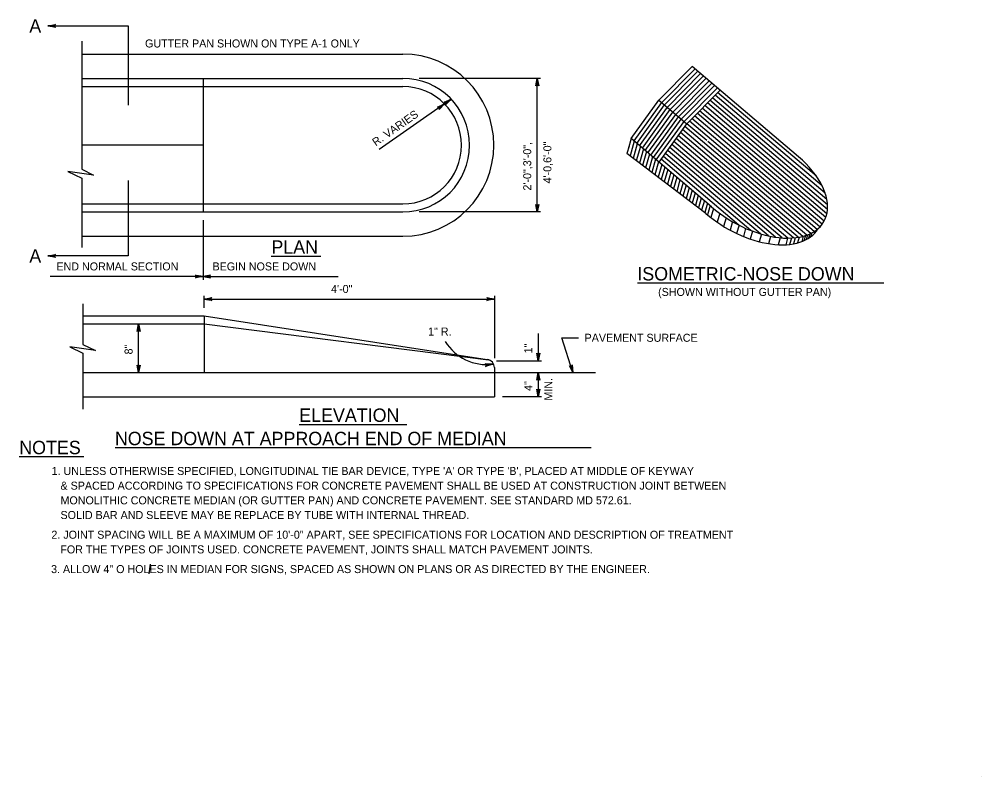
# Model space of a CAD drawing. Extents: x -49.1 to -41.9, y 44.5 to 54.6.
# Drawn here: x -49.07 to -41.86, y 44.46 to 50.14 of the extents above; entities that cross this region are included whole.
import ezdxf

# ---------------------------------------------------------------- set-up
doc = ezdxf.new("R2010")
doc.units = 0
for name, color, linetype in [('DETL-DIMS', 7, 'Continuous'), ('DETL-LINE', 7, 'Continuous'), ('DETL-NOTE', 7, 'Continuous'), ('DETL-PATT', 7, 'Continuous'), ('DETL-TITL', 7, 'Continuous'), ('TTLB-TEXT', 7, 'Continuous')]:
    doc.layers.add(name, color=color, linetype=linetype)

msp = doc.modelspace()

# ---------------------------------------------------------------- linework, layer by layer
at = {"layer": 'DETL-DIMS'}
for p, q in [((-48.8553, 50.0858), (-48.2538, 50.0858)), ((-48.2539, 50.0858), (-48.2539, 49.4918)), ((-45.1641, 49.6931), (-46.0747, 49.6931)), ((-45.1883, 48.6931), (-45.1883, 49.6931)), ((-45.8839, 49.5024), (-46.3726, 49.1601)), ((-45.8328, 49.5381), (-45.8838, 49.5024)), ((-48.2539, 48.9286), (-48.2539, 48.3637)), ((-45.1641, 48.6931), (-46.0747, 48.6931)), ((-47.6925, 48.6325), (-47.6925, 48.1858)), ((-48.2539, 48.3637), (-48.8553, 48.3637)), ((-47.6925, 48.2101), (-48.8389, 48.2101)), ((-47.6925, 48.2101), (-46.6795, 48.2101)), ((-47.6848, 47.9757), (-47.6848, 48.0656)), ((-47.6848, 48.0413), (-45.5099, 48.0413)), ((-45.5099, 48.0656), (-45.5099, 47.5984)), ((-48.1756, 47.4909), (-48.1756, 47.8545)), ((-45.1812, 47.7826), (-45.1812, 47.5795)), ((-44.9211, 47.491), (-45.0044, 47.7513)), ((-45.0044, 47.7513), (-44.8795, 47.7513)), ((-45.495, 47.5795), (-45.157, 47.5795)), ((-45.1812, 47.4909), (-45.1812, 47.3091)), ((-45.157, 47.3091), (-45.4493, 47.3091))]:
    msp.add_line(p, q, dxfattribs=at)
for points in [[(-48.8553, 50.0858), (-48.7988, 50.0964), (-48.8031, 50.0934), (-48.8054, 50.0896), (-48.806, 50.0858), (-48.8054, 50.0821), (-48.8031, 50.0783), (-48.7988, 50.0752), (-48.8553, 50.0858), (-48.8031, 50.0783), (-48.8054, 50.0821), (-48.8553, 50.0858), (-48.806, 50.0858), (-48.8054, 50.0896), (-48.8553, 50.0858), (-48.8031, 50.0934)], [(-45.1883, 49.6931), (-45.1777, 49.6366), (-45.1807, 49.6409), (-45.1845, 49.6432), (-45.1883, 49.6438), (-45.1921, 49.6432), (-45.1959, 49.6409), (-45.1989, 49.6366), (-45.1883, 49.6931), (-45.1959, 49.6409), (-45.1921, 49.6432), (-45.1883, 49.6931), (-45.1883, 49.6438), (-45.1845, 49.6432), (-45.1883, 49.6931), (-45.1807, 49.6409)], [(-45.1883, 49.6931), (-45.1777, 49.6366), (-45.1807, 49.6409), (-45.1845, 49.6432), (-45.1883, 49.6438), (-45.1921, 49.6432), (-45.1959, 49.6409), (-45.1989, 49.6366), (-45.1883, 49.6931), (-45.1959, 49.6409), (-45.1921, 49.6432), (-45.1883, 49.6931), (-45.1883, 49.6438), (-45.1845, 49.6432), (-45.1883, 49.6931), (-45.1807, 49.6409)], [(-45.8839, 49.5024), (-45.9241, 49.4613), (-45.9222, 49.4662), (-45.9226, 49.4706), (-45.9242, 49.4741), (-45.9269, 49.4769), (-45.9309, 49.4787), (-45.9362, 49.4786), (-45.8839, 49.5024), (-45.9309, 49.4787), (-45.9269, 49.4769), (-45.8839, 49.5024), (-45.9242, 49.4741), (-45.9226, 49.4706), (-45.8839, 49.5024), (-45.9222, 49.4662)], [(-45.8328, 49.5381), (-45.873, 49.497), (-45.8712, 49.502), (-45.8715, 49.5064), (-45.8732, 49.5099), (-45.8759, 49.5126), (-45.8799, 49.5144), (-45.8852, 49.5144), (-45.8328, 49.5381), (-45.8799, 49.5144), (-45.8759, 49.5126), (-45.8328, 49.5381), (-45.8732, 49.5099), (-45.8715, 49.5064), (-45.8328, 49.5381), (-45.8712, 49.502)], [(-45.1883, 48.6931), (-45.1989, 48.7496), (-45.1959, 48.7452), (-45.1921, 48.743), (-45.1883, 48.7423), (-45.1845, 48.743), (-45.1807, 48.7452), (-45.1777, 48.7496), (-45.1883, 48.6931), (-45.1807, 48.7452), (-45.1845, 48.743), (-45.1883, 48.6931), (-45.1883, 48.7423), (-45.1921, 48.743), (-45.1883, 48.6931), (-45.1959, 48.7452)], [(-48.8553, 48.3637), (-48.7988, 48.3743), (-48.8031, 48.3712), (-48.8054, 48.3675), (-48.806, 48.3637), (-48.8054, 48.3599), (-48.8031, 48.3561), (-48.7988, 48.3531), (-48.8553, 48.3637), (-48.8031, 48.3561), (-48.8054, 48.3599), (-48.8553, 48.3637), (-48.806, 48.3637), (-48.8054, 48.3675), (-48.8553, 48.3637), (-48.8031, 48.3712)], [(-47.6925, 48.2101), (-47.7489, 48.1995), (-47.7446, 48.2025), (-47.7423, 48.2063), (-47.7417, 48.2101), (-47.7423, 48.2139), (-47.7446, 48.2176), (-47.7489, 48.2207), (-47.6925, 48.2101), (-47.7446, 48.2176), (-47.7423, 48.2139), (-47.6925, 48.2101), (-47.7417, 48.2101), (-47.7423, 48.2063), (-47.6925, 48.2101), (-47.7446, 48.2025)], [(-47.6925, 48.2101), (-47.636, 48.1995), (-47.6403, 48.2025), (-47.6426, 48.2063), (-47.6432, 48.2101), (-47.6426, 48.2139), (-47.6403, 48.2176), (-47.636, 48.2207), (-47.6925, 48.2101), (-47.6403, 48.2176), (-47.6426, 48.2139), (-47.6925, 48.2101), (-47.6432, 48.2101), (-47.6426, 48.2063), (-47.6925, 48.2101), (-47.6403, 48.2025)], [(-47.6848, 48.0413), (-47.6283, 48.0519), (-47.6326, 48.0489), (-47.6349, 48.0451), (-47.6355, 48.0413), (-47.6349, 48.0375), (-47.6326, 48.0337), (-47.6283, 48.0307), (-47.6848, 48.0413), (-47.6326, 48.0337), (-47.6349, 48.0375), (-47.6848, 48.0413), (-47.6355, 48.0413), (-47.6349, 48.0451), (-47.6848, 48.0413), (-47.6326, 48.0489)], [(-47.6848, 48.0413), (-47.6283, 48.0519), (-47.6326, 48.0489), (-47.6349, 48.0451), (-47.6355, 48.0413), (-47.6349, 48.0375), (-47.6326, 48.0337), (-47.6283, 48.0307), (-47.6848, 48.0413), (-47.6326, 48.0337), (-47.6349, 48.0375), (-47.6848, 48.0413), (-47.6355, 48.0413), (-47.6349, 48.0451), (-47.6848, 48.0413), (-47.6326, 48.0489)], [(-45.5099, 48.0413), (-45.5664, 48.0307), (-45.562, 48.0337), (-45.5598, 48.0375), (-45.5591, 48.0413), (-45.5598, 48.0451), (-45.562, 48.0489), (-45.5664, 48.0519), (-45.5099, 48.0413), (-45.562, 48.0489), (-45.5598, 48.0451), (-45.5099, 48.0413), (-45.5591, 48.0413), (-45.5598, 48.0375), (-45.5099, 48.0413), (-45.562, 48.0337)], [(-48.1756, 47.8545), (-48.165, 47.798), (-48.168, 47.8024), (-48.1718, 47.8046), (-48.1756, 47.8053), (-48.1794, 47.8046), (-48.1831, 47.8024), (-48.1861, 47.798), (-48.1756, 47.8545), (-48.1831, 47.8024), (-48.1794, 47.8046), (-48.1756, 47.8545), (-48.1756, 47.8053), (-48.1718, 47.8046), (-48.1756, 47.8545), (-48.168, 47.8024)], [(-48.1756, 47.8545), (-48.165, 47.798), (-48.168, 47.8024), (-48.1718, 47.8046), (-48.1756, 47.8053), (-48.1794, 47.8046), (-48.1831, 47.8024), (-48.1861, 47.798), (-48.1756, 47.8545), (-48.1831, 47.8024), (-48.1794, 47.8046), (-48.1756, 47.8545), (-48.1756, 47.8053), (-48.1718, 47.8046), (-48.1756, 47.8545), (-48.168, 47.8024)], [(-45.1812, 47.5795), (-45.1918, 47.636), (-45.1888, 47.6317), (-45.185, 47.6294), (-45.1812, 47.6288), (-45.1774, 47.6294), (-45.1737, 47.6317), (-45.1706, 47.636), (-45.1812, 47.5795), (-45.1737, 47.6317), (-45.1774, 47.6294), (-45.1812, 47.5795), (-45.1812, 47.6288), (-45.185, 47.6294), (-45.1812, 47.5795), (-45.1888, 47.6317)], [(-45.1812, 47.5795), (-45.1918, 47.636), (-45.1888, 47.6317), (-45.185, 47.6294), (-45.1812, 47.6288), (-45.1774, 47.6294), (-45.1737, 47.6317), (-45.1706, 47.636), (-45.1812, 47.5795), (-45.1737, 47.6317), (-45.1774, 47.6294), (-45.1812, 47.5795), (-45.1812, 47.6288), (-45.185, 47.6294), (-45.1812, 47.5795), (-45.1888, 47.6317)], [(-48.1756, 47.4909), (-48.1861, 47.5474), (-48.1831, 47.543), (-48.1794, 47.5408), (-48.1756, 47.5401), (-48.1718, 47.5408), (-48.168, 47.543), (-48.165, 47.5474), (-48.1756, 47.4909), (-48.168, 47.543), (-48.1718, 47.5408), (-48.1756, 47.4909), (-48.1756, 47.5401), (-48.1794, 47.5408), (-48.1756, 47.4909), (-48.1831, 47.543)], [(-45.522, 47.5535), (-45.5766, 47.5356), (-45.5727, 47.5392), (-45.571, 47.5433), (-45.5708, 47.5471), (-45.572, 47.5508), (-45.5747, 47.5542), (-45.5794, 47.5566), (-45.522, 47.5535), (-45.5747, 47.5542), (-45.572, 47.5508), (-45.522, 47.5535), (-45.5708, 47.5471), (-45.571, 47.5433), (-45.522, 47.5535), (-45.5727, 47.5392)], [(-44.9211, 47.491), (-44.9484, 47.5416), (-44.9442, 47.5384), (-44.9399, 47.5374), (-44.9361, 47.5379), (-44.9327, 47.5397), (-44.9298, 47.543), (-44.9282, 47.5481), (-44.9211, 47.491), (-44.9298, 47.543), (-44.9327, 47.5397), (-44.9211, 47.491), (-44.9361, 47.5379), (-44.9399, 47.5374), (-44.9211, 47.491), (-44.9442, 47.5384)], [(-45.1812, 47.4909), (-45.1706, 47.4344), (-45.1737, 47.4387), (-45.1774, 47.441), (-45.1812, 47.4416), (-45.185, 47.441), (-45.1888, 47.4387), (-45.1918, 47.4344), (-45.1812, 47.4909), (-45.1888, 47.4387), (-45.185, 47.441), (-45.1812, 47.4909), (-45.1812, 47.4416), (-45.1774, 47.441), (-45.1812, 47.4909), (-45.1737, 47.4387)], [(-45.1812, 47.3091), (-45.1918, 47.3655), (-45.1888, 47.3612), (-45.185, 47.359), (-45.1812, 47.3583), (-45.1774, 47.359), (-45.1737, 47.3612), (-45.1706, 47.3655), (-45.1812, 47.3091), (-45.1737, 47.3612), (-45.1774, 47.359), (-45.1812, 47.3091), (-45.1812, 47.3583), (-45.185, 47.359), (-45.1812, 47.3091), (-45.1888, 47.3612)]]:
    msp.add_lwpolyline(points, dxfattribs=at)
msp.add_arc((-45.5694, 47.9137), 0.3633, 211.7192, 277.49182, dxfattribs=at)
at = {"layer": 'DETL-LINE'}
for p, q in [((-48.6015, 49.9728), (-48.6015, 49.0124)), ((-48.6015, 49.8749), (-46.1959, 49.8749)), ((-44.2766, 49.5298), (-44.027, 49.7822)), ((-43.2303, 49.1071), (-44.027, 49.7822)), ((-48.6015, 49.6931), (-46.1959, 49.6931)), ((-47.6925, 49.6931), (-47.6925, 48.6931)), ((-48.6015, 49.6325), (-46.1959, 49.6325)), ((-44.0685, 49.3535), (-43.8189, 49.6059)), ((-44.4846, 49.2422), (-44.2766, 49.5298)), ((-44.2766, 49.5298), (-44.0685, 49.3535)), ((-44.2765, 49.0659), (-44.0685, 49.3535)), ((-43.9191, 49.2277), (-44.0681, 49.354)), ((-47.6925, 49.1931), (-48.6015, 49.1931)), ((-44.5004, 49.1868), (-44.5167, 49.1299)), ((-44.4846, 49.2422), (-44.5074, 49.1625)), ((-43.8828, 48.7323), (-44.4846, 49.2422)), ((-43.1144, 48.5459), (-43.9113, 49.2211)), ((-43.9251, 48.6824), (-44.5167, 49.1299)), ((-48.6015, 48.9459), (-48.6015, 48.4276)), ((-48.6015, 48.7537), (-46.1959, 48.7537)), ((-48.6015, 48.6931), (-46.1959, 48.6931)), ((-48.6015, 48.5112), (-46.1959, 48.5112)), ((-48.5938, 48.0047), (-48.5938, 47.7021)), ((-48.5938, 47.9151), (-47.6848, 47.9151)), ((-47.6848, 47.9151), (-47.6848, 47.4909)), ((-47.6848, 47.9151), (-45.5636, 47.588)), ((-48.5938, 47.8545), (-47.6848, 47.8545)), ((-47.6848, 47.8545), (-45.5533, 47.5859)), ((-48.5938, 47.6355), (-48.5938, 47.2157)), ((-45.5099, 47.5277), (-45.5099, 47.4909)), ((-48.5938, 47.4909), (-45.5099, 47.4909)), ((-45.5243, 47.4909), (-44.7516, 47.4909)), ((-45.5099, 47.4909), (-45.5099, 47.3091)), ((-48.5938, 47.3091), (-45.5099, 47.3091))]:
    msp.add_line(p, q, dxfattribs=at)
for points in [[(-48.6015, 49.0124), (-48.5138, 48.9694), (-48.706, 48.9956), (-48.6015, 48.9459)], [(-48.5938, 47.7021), (-48.4999, 47.6561), (-48.6921, 47.6823), (-48.5938, 47.6355)]]:
    msp.add_lwpolyline(points, dxfattribs=at)
for centre, radius, start, end in [((-46.1959, 49.1931), 0.6818, 270, 90), ((-46.1959, 49.1931), 0.5, 270, 90), ((-46.1959, 49.1931), 0.4394, 270, 90), ((-45.5705, 47.5277), 0.0606, 0, 83.44779)]:
    msp.add_arc(centre, radius, start, end, dxfattribs=at)
for centre, end_param in [((-43.556, 48.9192), 7.534935), ((-43.5983, 48.8693), 6.275775)]:
    msp.add_ellipse(centre, major_axis=(0.5143, -0.2998), ratio=0.57735, start_param=4.390639, end_param=end_param, dxfattribs=at)
at = {"layer": 'DETL-NOTE'}
for p, q in [((-49.0701, 46.8626), (-48.5855, 46.8626)), ((-48.0958, 45.9837), (-48.0862, 46.0569))]:
    msp.add_line(p, q, dxfattribs=at)
at = {"layer": 'DETL-PATT'}
for p, q in [((-44.2557, 49.5121), (-44.0061, 49.7645)), ((-44.2349, 49.4944), (-43.9853, 49.7468)), ((-44.214, 49.4768), (-43.9644, 49.7291)), ((-44.1931, 49.4591), (-43.9435, 49.7114)), ((-44.1722, 49.4414), (-43.9227, 49.6938)), ((-44.1514, 49.4237), (-43.9018, 49.6761)), ((-44.1305, 49.406), (-43.8809, 49.6584)), ((-44.1096, 49.3884), (-43.8601, 49.6407)), ((-44.0888, 49.3707), (-43.8392, 49.623)), ((-43.0316, 48.8332), (-43.8726, 49.5458)), ((-43.0546, 48.8885), (-43.855, 49.5666)), ((-43.097, 48.9601), (-43.8373, 49.5874)), ((-44.4637, 49.2245), (-44.2545, 49.5138)), ((-44.4428, 49.2068), (-44.2349, 49.4944)), ((-44.422, 49.1891), (-44.214, 49.4768)), ((-43.014, 48.711), (-43.9334, 49.4901)), ((-43.0139, 48.7467), (-43.9142, 49.5096)), ((-43.0192, 48.7869), (-43.895, 49.529)), ((-44.4011, 49.1715), (-44.1931, 49.4591)), ((-44.3802, 49.1538), (-44.1722, 49.4414)), ((-44.3594, 49.1361), (-44.1514, 49.4237)), ((-44.3385, 49.1184), (-44.1305, 49.406)), ((-43.0535, 48.6015), (-44.0104, 49.4123)), ((-43.0387, 48.6247), (-43.9911, 49.4318)), ((-43.027, 48.6505), (-43.9719, 49.4512)), ((-43.0186, 48.6792), (-43.9527, 49.4707)), ((-44.3176, 49.1007), (-44.1096, 49.3884)), ((-44.2967, 49.083), (-44.0888, 49.3707)), ((-43.14, 48.5318), (-44.0842, 49.3319)), ((-43.0914, 48.5621), (-44.0488, 49.3734)), ((-43.0711, 48.5806), (-44.0296, 49.3929)), ((-43.2331, 48.5034), (-44.1322, 49.2654)), ((-43.1992, 48.5105), (-44.1162, 49.2875)), ((-43.1683, 48.52), (-44.1002, 49.3097)), ((-44.4617, 49.2228), (-44.4934, 49.1122)), ((-44.4389, 49.2035), (-44.47, 49.0946)), ((-43.354, 48.4987), (-44.1803, 49.1989)), ((-43.3101, 48.4972), (-44.1643, 49.221)), ((-43.2699, 48.4989), (-44.1483, 49.2432)), ((-44.4161, 49.1841), (-44.4467, 49.077)), ((-44.3933, 49.1648), (-44.4234, 49.0593)), ((-44.3704, 49.1454), (-44.4001, 49.0417)), ((-44.3476, 49.1261), (-44.3768, 49.024)), ((-43.5169, 48.5295), (-44.2252, 49.1296)), ((-43.4561, 48.5137), (-44.2076, 49.1505)), ((-43.4024, 48.5039), (-44.1964, 49.1767)), ((-44.3247, 49.1067), (-44.3534, 49.0064)), ((-44.3019, 49.0874), (-44.3301, 48.9887)), ((-44.2791, 49.068), (-44.3068, 48.9711)), ((-44.2562, 49.0487), (-44.2835, 48.9535)), ((-43.6777, 48.5942), (-44.2605, 49.088)), ((-43.588, 48.554), (-44.2429, 49.1089)), ((-44.2334, 49.0294), (-44.2601, 48.9358)), ((-44.2106, 49.01), (-44.2368, 48.9182)), ((-44.1877, 48.9906), (-44.2135, 48.9005)), ((-44.1649, 48.9713), (-44.1902, 48.8829)), ((-44.1421, 48.952), (-44.1669, 48.8652)), ((-44.1192, 48.9326), (-44.1435, 48.8476)), ((-44.0964, 48.9133), (-44.1202, 48.8299)), ((-44.0736, 48.8939), (-44.0969, 48.8123)), ((-44.0507, 48.8746), (-44.0736, 48.7946)), ((-44.0279, 48.8552), (-44.0502, 48.777)), ((-44.0051, 48.8359), (-44.0269, 48.7594)), ((-43.9822, 48.8165), (-44.0036, 48.7417)), ((-43.9594, 48.7972), (-43.9803, 48.7241)), ((-43.9366, 48.7778), (-43.957, 48.7064)), ((-43.9137, 48.7585), (-43.9336, 48.6888)), ((-43.8926, 48.7406), (-43.9124, 48.6714)), ((-43.8681, 48.7197), (-43.8876, 48.6513)), ((-43.8218, 48.6832), (-43.8408, 48.6166)), ((-43.7745, 48.6503), (-43.793, 48.5853)), ((-43.7262, 48.6206), (-43.7444, 48.5571)), ((-43.6771, 48.5939), (-43.6948, 48.5319)), ((-43.6272, 48.5702), (-43.6445, 48.5097)), ((-43.5764, 48.5495), (-43.5932, 48.4904)), ((-43.1321, 48.5358), (-43.1403, 48.5071)), ((-43.509, 48.5271), (-43.5253, 48.4701)), ((-43.44, 48.5104), (-43.4557, 48.4556)), ((-43.3693, 48.5), (-43.3841, 48.448)), ((-43.3133, 48.4972), (-43.3274, 48.448)), ((-43.2847, 48.4979), (-43.2984, 48.4503)), ((-43.2557, 48.5003), (-43.2688, 48.4546)), ((-43.2261, 48.5046), (-43.2385, 48.4614)), ((-43.1958, 48.5114), (-43.2073, 48.4713)), ((-43.1799, 48.5161), (-43.1908, 48.478)), ((-43.1646, 48.5214), (-43.1748, 48.4856)), ((-43.1474, 48.5284), (-43.1567, 48.4959))]:
    msp.add_line(p, q, dxfattribs=at)
at = {"layer": 'DETL-TITL'}
for p, q in [((-47.1828, 48.3622), (-46.8114, 48.3622)), ((-44.4371, 48.1615), (-42.5925, 48.1615)), ((-46.9723, 47.1032), (-46.166, 47.1032)), ((-48.3521, 46.9286), (-44.7856, 46.9286))]:
    msp.add_line(p, q, dxfattribs=at)
at = {"layer": 'TTLB-TEXT'}
msp.add_line((-41.8582, 44.4649), (-41.8582, 44.4649), dxfattribs=at)

# ---------------------------------------------------------------- texts
at = {"layer": 'DETL-NOTE'}
for s, height, p in [('GUTTER PAN SHOWN ON TYPE A-1 ONLY', 0.06, (-48.1276, 49.9247)), ('END NORMAL SECTION', 0.06, (-48.7916, 48.2555)), ('BEGIN NOSE DOWN', 0.06, (-47.6219, 48.2555)), ('4\'-0"', 0.06, (-46.7336, 48.0868)), ('(SHOWN WITHOUT GUTTER PAN)', 0.06, (-44.2832, 48.0644)), ('1" R.', 0.06, (-46.0067, 47.7681)), ('PAVEMENT SURFACE', 0.06, (-44.834, 47.7213)), ('NOTES', 0.1, (-49.0701, 46.8797)), ("1. UNLESS OTHERWISE SPECIFIED, LONGITUDINAL TIE BAR DEVICE, TYPE 'A' OR TYPE 'B', PLACED AT MIDDLE OF KEYWAY", 0.06, (-48.8278, 46.7241)), ('   & SPACED ACCORDING TO SPECIFICATIONS FOR CONCRETE PAVEMENT SHALL BE USED AT CONSTRUCTION JOINT BETWEEN', 0.06, (-48.8278, 46.6141)), ('   MONOLITHIC CONCRETE MEDIAN (OR GUTTER PAN) AND CONCRETE PAVEMENT. SEE STANDARD MD 572.61. ', 0.06, (-48.8278, 46.5041)), ('   SOLID BAR AND SLEEVE MAY BE REPLACE BY TUBE WITH INTERNAL THREAD. ', 0.06, (-48.8278, 46.3941)), ('2. JOINT SPACING WILL BE A MAXIMUM OF 10\'-0" APART, SEE SPECIFICATIONS FOR LOCATION AND DESCRIPTION OF TREATMENT', 0.06, (-48.8291, 46.2468)), ('   FOR THE TYPES OF JOINTS USED. CONCRETE PAVEMENT, JOINTS SHALL MATCH PAVEMENT JOINTS.', 0.06, (-48.8291, 46.1368)), ('3. ALLOW 4" O HOLES IN MEDIAN FOR SIGNS, SPACED AS SHOWN ON PLANS OR AS DIRECTED BY THE ENGINEER.', 0.06, (-48.8317, 45.9895))]:
    msp.add_text(s, height=height, dxfattribs=at).set_placement(p)
for s, rotation, p in [('R. VARIES', 35.00703, (-46.3987, 49.1832)), ('2\'-0",3\'-0",', 90, (-45.2338, 48.8534)), ('4\'-0,6\'-0"', 90, (-45.0828, 48.9067)), ('8"', 90, (-48.221, 47.6264)), ('1"', 90, (-45.2267, 47.6347)), ('4"', 90, (-45.2267, 47.3536)), ('MIN.', 90, (-45.0758, 47.2808))]:
    msp.add_text(s, height=0.06, rotation=rotation, dxfattribs=at).set_placement(p)
at = {"layer": 'DETL-TITL'}
for s, p in [('A', (-48.9947, 50.0358)), ('PLAN', (-47.1808, 48.3808)), ('A', (-48.9947, 48.3137)), ('ISOMETRIC-NOSE DOWN', (-44.439, 48.1801)), ('ELEVATION', (-46.9723, 47.1218)), ('NOSE DOWN AT APPROACH END OF MEDIAN', (-48.3533, 46.9472))]:
    msp.add_text(s, height=0.1, dxfattribs=at).set_placement(p)

doc.saveas('drawing.dxf')
